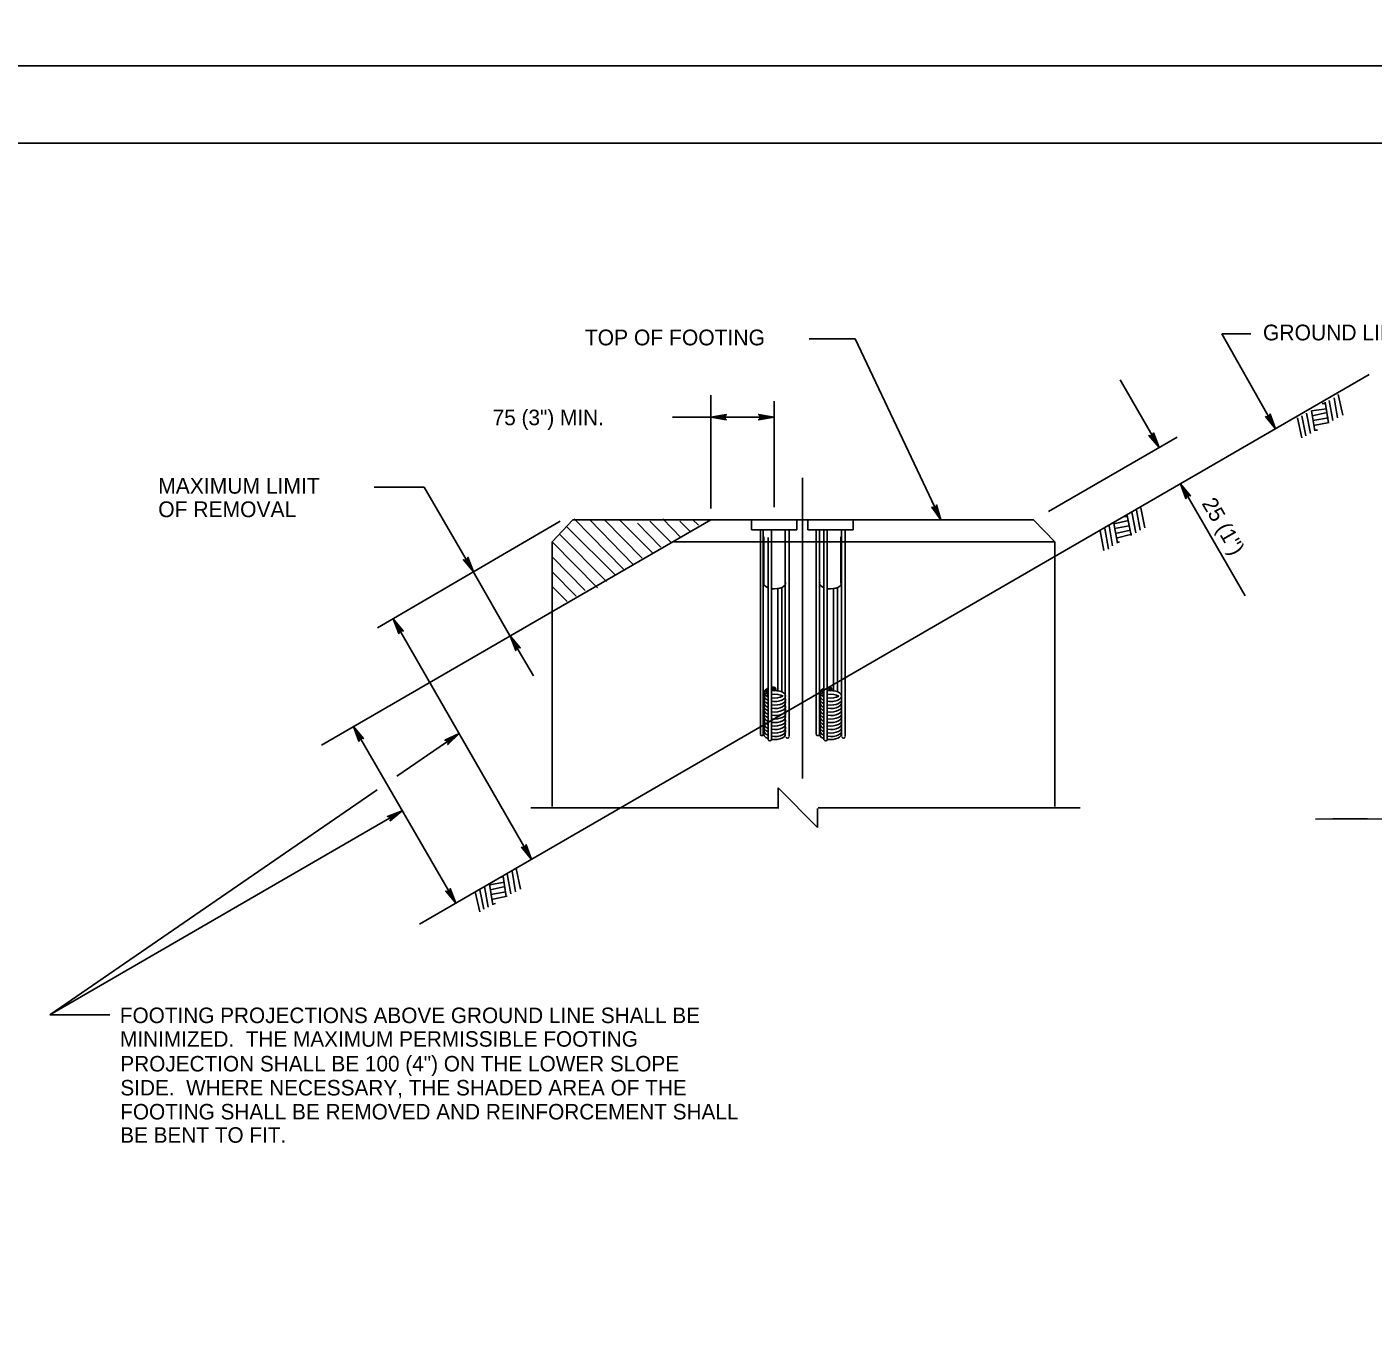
# Model space of a CAD drawing. Extents: x 637580 to 641008, y 294594 to 295782.
# Drawn here: x 640305.6 to 640565.8, y 294944.4 to 295195.1 of the extents above; entities that cross this region are included whole.
import ezdxf

# ---------------------------------------------------------------- set-up
doc = ezdxf.new("R2010")
doc.units = 0
for name, color, linetype in [('1', 7, 'Continuous'), ('2', 7, 'Continuous'), ('3', 7, 'Continuous'), ('PLT-BNDY', 7, 'Continuous')]:
    doc.layers.add(name, color=color, linetype=linetype)

# ---------------------------------------------------------------- blocks, each defined once
blk = doc.blocks.new('RARROW')
at = {"layer": '3'}
blk.add_lwpolyline([(-2.2695, 0.285), (-2.184875, 0.12075), (0, 0), (-2.2695, 0.285), (-2.38575, 0.384625), (0, 0), (-2.183125, -0.108), (-2.262875, -0.2705), (0, 0), (-2.38575, -0.379125), (-2.262875, -0.2705)], dxfattribs=at)

msp = doc.modelspace()

# ---------------------------------------------------------------- linework, layer by layer
at = {"layer": '1'}
for p, q in [((640143.31, 295172.63), (640929.31, 295172.63)), ((640559.02, 295124.06), (640559.9, 295120.06)), ((640556.52, 295122.31), (640555.9, 295122.31)), ((640556.52, 295122.56), (640557.15, 295118.56)), ((640557.27, 295122.93), (640558.02, 295119.06)), ((640558.27, 295123.43), (640558.9, 295119.56)), ((640551.15, 295119.56), (640552.02, 295115.68)), ((640552.02, 295119.93), (640552.77, 295116.06)), ((640552.9, 295120.43), (640553.65, 295116.56)), ((640556.77, 295121.31), (640553.9, 295120.93)), ((640553.9, 295120.93), (640554.52, 295117.06)), ((640556.9, 295120.56), (640554.02, 295119.93)), ((640557.15, 295119.56), (640554.15, 295119.06)), ((640557.27, 295118.68), (640554.27, 295118.06)), ((640555.02, 295117.18), (640554.52, 295117.18)), ((640518.4, 295100.56), (640517.77, 295100.43)), ((640518.27, 295100.68), (640519.02, 295096.81)), ((640519.15, 295101.31), (640519.9, 295097.31)), ((640520.02, 295101.68), (640520.77, 295097.81)), ((640520.9, 295102.18), (640521.65, 295098.31)), ((640513.9, 295098.18), (640514.65, 295094.18)), ((640514.77, 295098.68), (640515.4, 295094.81)), ((640518.52, 295099.68), (640515.65, 295099.06)), ((640515.65, 295099.18), (640516.4, 295095.31)), ((640518.65, 295098.68), (640515.77, 295098.18)), ((640513.02, 295097.68), (640513.77, 295093.93)), ((640518.9, 295097.81), (640516.02, 295097.18)), ((640519.15, 295097.06), (640516.15, 295096.31)), ((640516.77, 295095.56), (640516.4, 295095.43)), ((640397.65, 295030.81), (640397.02, 295030.68)), ((640397.65, 295030.93), (640398.27, 295026.93)), ((640398.4, 295031.43), (640399.15, 295027.56)), ((640399.4, 295031.93), (640400.02, 295027.93)), ((640400.15, 295032.43), (640401.02, 295028.43)), ((640392.27, 295027.93), (640393.15, 295024.06)), ((640393.15, 295028.31), (640393.9, 295024.56)), ((640394.02, 295028.93), (640394.77, 295024.93)), ((640397.9, 295029.81), (640395.02, 295029.31)), ((640395.02, 295029.43), (640395.65, 295025.43)), ((640398.02, 295028.93), (640395.15, 295028.31)), ((640398.15, 295027.93), (640395.27, 295027.43)), ((640398.4, 295027.06), (640395.4, 295026.43)), ((640396.15, 295025.68), (640395.65, 295025.56))]:
    msp.add_line(p, q, dxfattribs=at)
msp.add_ellipse((640561.36, 294260.59), major_axis=(0, 781.44), ratio=0.996388, start_param=6.016663, end_param=6.291815, dxfattribs=at)
at = {"layer": '2'}
for p, q in [((640456.8, 295134.86), (640465.69, 295134.86)), ((640465.69, 295134.86), (640482.26, 295099.81)), ((640536.54, 295135.81), (640546.9, 295117.43)), ((640536.54, 295135.81), (640542.15, 295135.81)), ((640381.52, 295021.68), (640565.02, 295127.93)), ((640516.9, 295126.93), (640524.4, 295113.81)), ((640437.77, 295102.06), (640437.77, 295123.93)), ((640450.02, 295102.31), (640450.02, 295122.81)), ((640430.37, 295119.68), (640450.02, 295119.68)), ((640503.02, 295101.43), (640527.9, 295115.81)), ((640372.75, 295106.18), (640382.4, 295106.18)), ((640382.4, 295106.18), (640392.15, 295089.43)), ((640455.52, 295107.93), (640455.52, 295049.81)), ((640528.54, 295106.81), (640541.02, 295085.14)), ((640362.52, 295056.31), (640437.77, 295099.81)), ((640373.4, 295078.93), (640408.65, 295099.56)), ((640407.15, 295095.56), (640411.15, 295099.81)), ((640409.9, 295098.56), (640419.4, 295089.06)), ((640500.15, 295099.81), (640411.15, 295099.81)), ((640411.4, 295100.06), (640420.9, 295090.31)), ((640414.4, 295099.81), (640422.77, 295091.18)), ((640417.27, 295099.81), (640424.52, 295092.43)), ((640420.27, 295099.68), (640426.65, 295093.31)), ((640423.65, 295099.18), (640428.15, 295094.56)), ((640426.02, 295099.56), (640430.15, 295095.43)), ((640428.52, 295100.06), (640432.02, 295096.43)), ((640431.77, 295099.56), (640433.9, 295097.43)), ((640434.27, 295099.93), (640435.4, 295098.81)), ((640454.4, 295099.81), (640445.65, 295099.81)), ((640445.65, 295099.81), (640445.65, 295097.93)), ((640454.4, 295097.93), (640445.65, 295097.93)), ((640447.4, 295097.93), (640447.4, 295058.31)), ((640447.9, 295058.31), (640447.9, 295097.93)), ((640452.9, 295057.93), (640452.9, 295097.93)), ((640454.4, 295099.81), (640454.4, 295097.93)), ((640465.27, 295099.81), (640456.52, 295099.81)), ((640456.52, 295099.81), (640456.52, 295097.93)), ((640465.27, 295097.93), (640456.52, 295097.93)), ((640458.15, 295097.93), (640458.15, 295058.31)), ((640458.77, 295058.31), (640458.77, 295097.93)), ((640459.65, 295097.93), (640459.65, 295057.31)), ((640460.27, 295057.18), (640460.27, 295097.93)), ((640463.02, 295097.93), (640463.02, 295057.93)), ((640463.77, 295057.93), (640463.77, 295097.93)), ((640465.27, 295099.81), (640465.27, 295097.93)), ((640500.15, 295099.81), (640504.27, 295095.56)), ((640407.15, 295095.56), (640407.15, 295044.43)), ((640407.15, 295095.56), (640415.9, 295086.68)), ((640408.52, 295097.06), (640417.65, 295087.93)), ((640504.27, 295095.56), (640430.65, 295095.56)), ((640448.02, 295087.56), (640448.02, 295096.56)), ((640448.9, 295096.43), (640448.9, 295057.31)), ((640449.52, 295057.18), (640449.52, 295097.81)), ((640452.15, 295097.68), (640452.15, 295057.93)), ((640452.15, 295087.56), (640452.15, 295096.56)), ((640458.77, 295087.56), (640458.77, 295096.56)), ((640462.9, 295087.56), (640462.9, 295096.56)), ((640504.27, 295095.56), (640504.27, 295044.43)), ((640407.15, 295092.68), (640413.52, 295086.18)), ((640392.15, 295089.43), (640398.9, 295077.56)), ((640407.15, 295089.81), (640411.77, 295085.06)), ((640407.15, 295086.93), (640410.02, 295084.06)), ((640450.77, 295086.56), (640450.77, 295066.68)), ((640451.52, 295066.56), (640451.52, 295086.56)), ((640461.52, 295086.56), (640461.52, 295066.68)), ((640462.27, 295066.56), (640462.27, 295086.56)), ((640376.4, 295080.68), (640403.15, 295034.18)), ((640398.9, 295077.56), (640403.52, 295069.68)), ((640368.72, 295059.89), (640388.5, 295025.72)), ((640377.08, 295050.26), (640389.13, 295058.54)), ((640448.9, 295057.56), (640448.9, 295057.31)), ((640449.52, 295057.31), (640449.52, 295057.56)), ((640450.15, 295057.43), (640450.15, 295057.43)), ((640450.15, 295057.43), (640450.15, 295057.43)), ((640459.65, 295057.56), (640459.65, 295057.31)), ((640460.27, 295057.31), (640460.27, 295057.56)), ((640460.9, 295057.43), (640460.9, 295057.43)), ((640460.9, 295057.43), (640460.9, 295057.43)), ((640310.02, 295004.18), (640373.3, 295047.67)), ((640450.78, 295044.01), (640450.78, 295048.01)), ((640450.78, 295048.01), (640458.41, 295040.38)), ((640310.02, 295004.18), (640378.14, 295043.61)), ((640450.9, 295044.18), (640403.02, 295044.18)), ((640458.41, 295040.38), (640458.41, 295044.01)), ((640509.15, 295044.18), (640458.52, 295044.18)), ((640310.02, 295004.18), (640321.65, 295004.18))]:
    msp.add_line(p, q, dxfattribs=at)
for centre, major_axis, ratio, start_param, end_param in [((640450.27, 295087.53), (2.27, 0), 0.460673, 2.912303, 4.028509), ((640449.97, 295087.54), (2.27, 0), 0.460673, 4.516666, 6.442696), ((640461.08, 295087.53), (2.27, 0), 0.460673, 2.912303, 4.028509), ((640460.78, 295087.54), (2.27, 0), 0.460673, 4.516666, 6.442696), ((640450.15, 295066.43), (-2.08, 0), 0.502134, 5.849045, 7.178118), ((640450.13, 295066.44), (-2.08, 0), 0.502134, 5.351446, 7.172319), ((640448.33, 295066.66), (0, 0.243), 0.996388, 3.791362, 5.77982), ((640448.53, 295066.83), (0, 0.243), 0.996388, 3.791362, 5.77982), ((640450.13, 295066.44), (-2.08, 0), 0.502134, 4.76759, 5.015799), ((640450.17, 295065.78), (-2.08, 0), 0.502134, 1.274353, 5.008427), ((640449.58, 295067.15), (0, 0.243), 0.996388, 3.791362, 5.77982), ((640449.87, 295067.15), (0, 0.243), 0.996388, 3.791362, 5.77982), ((640449.98, 295067.14), (0, 0.357), 0.996388, 3.239859, 6.022487), ((640460.96, 295066.43), (-2.08, 0), 0.502134, 5.849045, 7.178118), ((640460.94, 295066.44), (-2.08, 0), 0.502134, 5.351446, 7.172319), ((640459.14, 295066.66), (0, 0.243), 0.996388, 3.791362, 5.77982), ((640459.34, 295066.83), (0, 0.243), 0.996388, 3.791362, 5.77982), ((640460.94, 295066.44), (-2.08, 0), 0.502134, 4.76759, 5.015799), ((640460.98, 295065.78), (-2.08, 0), 0.502134, 1.274353, 5.008427), ((640460.39, 295067.15), (0, 0.243), 0.996388, 3.791362, 5.77982), ((640460.68, 295067.15), (0, 0.243), 0.996388, 3.791362, 5.77982), ((640460.79, 295067.14), (0, 0.357), 0.996388, 3.239859, 6.022487), ((640450.15, 295064.4), (-2.08, 0), 0.502134, 5.919723, 7.178118), ((640450.16, 295065.08), (-2.08, 0), 0.502134, 5.946798, 7.171813), ((640450.16, 295065.76), (-2.08, 0), 0.502134, 5.393334, 7.171813), ((640450.16, 295065.08), (-2.08, 0), 0.502134, 5.393334, 5.574261), ((640450.16, 295065.08), (-2.08, 0), 0.502134, 5.393334, 5.569266), ((640448.5, 295066.08), (0, 0.243), 0.996388, 3.791362, 5.77982), ((640450.16, 295065.08), (-2.08, 0), 0.502134, 3.844502, 5.011675), ((640450.15, 295066.43), (-2.08, 0), 0.502134, 1.274353, 2.407384), ((640450.15, 295064.4), (-2.08, 0), 0.502134, 1.274353, 3.486745), ((640450.16, 295063.73), (-2.08, 0), 0.502134, 1.27062, 3.503952), ((640450.17, 295065.07), (-2.08, 0), 0.502134, 1.274353, 3.473428), ((640450.13, 295066.44), (-2.08, 0), 0.502134, 1.299271, 2.390101), ((640460.96, 295064.4), (-2.08, 0), 0.502134, 5.919723, 7.178118), ((640460.97, 295065.08), (-2.08, 0), 0.502134, 5.946798, 7.171813), ((640460.97, 295065.76), (-2.08, 0), 0.502134, 5.393334, 7.171813), ((640460.97, 295065.08), (-2.08, 0), 0.502134, 5.393334, 5.574261), ((640460.97, 295065.08), (-2.08, 0), 0.502134, 5.393334, 5.569266), ((640459.31, 295066.08), (0, 0.243), 0.996388, 3.791362, 5.77982), ((640460.97, 295065.08), (-2.08, 0), 0.502134, 3.844502, 5.011675), ((640460.96, 295066.43), (-2.08, 0), 0.502134, 1.274353, 2.407384), ((640460.96, 295064.4), (-2.08, 0), 0.502134, 1.274353, 3.486745), ((640460.97, 295063.73), (-2.08, 0), 0.502134, 1.27062, 3.503952), ((640460.98, 295065.07), (-2.08, 0), 0.502134, 1.274353, 3.473428), ((640460.94, 295066.44), (-2.08, 0), 0.502134, 1.299271, 2.390101), ((640450.16, 295063.73), (-2.08, 0), 0.502134, 5.937119, 7.171813), ((640450.16, 295061.69), (-2.08, 0), 0.502134, 5.946798, 7.171813), ((640450.17, 295063.05), (-2.08, 0), 0.502134, 5.955741, 7.164478), ((640450.17, 295062.37), (-2.08, 0), 0.502134, 5.965552, 7.164478), ((640450.17, 295063.05), (-2.08, 0), 0.502134, 1.264877, 3.495986), ((640450.17, 295062.37), (-2.08, 0), 0.502134, 1.264877, 3.488314), ((640450.16, 295061.69), (-2.08, 0), 0.502134, 1.27062, 3.451822), ((640460.97, 295063.73), (-2.08, 0), 0.502134, 5.937119, 7.171813), ((640460.97, 295061.69), (-2.08, 0), 0.502134, 5.946798, 7.171813), ((640460.98, 295063.05), (-2.08, 0), 0.502134, 5.955741, 7.164478), ((640460.98, 295062.37), (-2.08, 0), 0.502134, 5.965552, 7.164478), ((640460.98, 295063.05), (-2.08, 0), 0.502134, 1.264877, 3.495986), ((640460.98, 295062.37), (-2.08, 0), 0.502134, 1.264877, 3.488314), ((640460.97, 295061.69), (-2.08, 0), 0.502134, 1.27062, 3.451822), ((640450.15, 295060.34), (-2.08, 0), 0.502134, 5.938832, 7.178118), ((640450.17, 295061.02), (-2.08, 0), 0.502134, 5.963088, 7.164478), ((640450.17, 295059.66), (-2.08, 0), 0.502134, 5.96802, 7.164478), ((640450.17, 295058.99), (-2.08, 0), 0.502134, 5.972967, 7.164478), ((640450.17, 295061.02), (-2.08, 0), 0.502134, 1.264877, 3.483183), ((640450.15, 295060.34), (-2.08, 0), 0.502134, 1.274353, 3.465537), ((640450.17, 295059.66), (-2.08, 0), 0.502134, 1.264877, 3.503379), ((640450.17, 295058.99), (-2.08, 0), 0.502134, 1.264877, 3.485633), ((640460.96, 295060.34), (-2.08, 0), 0.502134, 5.938832, 7.178118), ((640460.98, 295061.02), (-2.08, 0), 0.502134, 5.963088, 7.164478), ((640460.98, 295059.66), (-2.08, 0), 0.502134, 5.96802, 7.164478), ((640460.98, 295058.99), (-2.08, 0), 0.502134, 5.972967, 7.164478), ((640460.98, 295061.02), (-2.08, 0), 0.502134, 1.264877, 3.483183), ((640460.96, 295060.34), (-2.08, 0), 0.502134, 1.274353, 3.465537), ((640460.98, 295059.66), (-2.08, 0), 0.502134, 1.264877, 3.503379), ((640460.98, 295058.99), (-2.08, 0), 0.502134, 1.264877, 3.485633), ((640447.68, 295058.55), (0, -0.425), 0.996388, 5.360294, 7.206077), ((640450.1, 295058.39), (-2.08, 0), 0.502134, 5.966419, 7.210371), ((640449.2, 295057.56), (0, -0.425), 0.996388, 5.360294, 7.206077), ((640450.1, 295058.39), (-2.08, 0), 0.502134, 1.288679, 3.37371), ((640452.61, 295058.05), (0, -0.425), 0.996388, 5.360294, 7.206077), ((640458.49, 295058.55), (0, -0.425), 0.996388, 5.360294, 7.206077), ((640460.91, 295058.39), (-2.08, 0), 0.502134, 5.966419, 7.210371), ((640460.01, 295057.56), (0, -0.425), 0.996388, 5.360294, 7.206077), ((640460.91, 295058.39), (-2.08, 0), 0.502134, 1.288679, 3.37371), ((640463.42, 295058.05), (0, -0.425), 0.996388, 5.360294, 7.206077)]:
    msp.add_ellipse(centre, major_axis=major_axis, ratio=ratio, start_param=start_param, end_param=end_param, dxfattribs=at)
at = {"layer": 'PLT-BNDY'}
for points in [[(640103.31, 295781.63), (640944.31, 295781.63), (640944.31, 295187.63), (640103.31, 295187.63)], [(640103.31, 295187.63), (640944.31, 295187.63), (640944.31, 294593.63), (640103.31, 294593.63)]]:
    msp.add_lwpolyline(points, close=True, dxfattribs=at)

# ---------------------------------------------------------------- block references
at = {"layer": '2'}
for p, xscale, yscale, rotation in [((640437.77, 295119.68), 1.2574347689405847, 1.3092961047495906, 180), ((640546.9, 295117.43), 1.257434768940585, 1.3092961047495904, -60.41609152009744), ((640524.4, 295113.81), 1.2574347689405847, 1.3092961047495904, -59.68635191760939), ((640528.54, 295106.81), 1.257434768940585, 1.3092961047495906, 120.03222654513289), ((640482.26, 295099.81), 1.2574347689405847, 1.3092961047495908, -64.63743865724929), ((640391.94, 295089.78), 1.2574347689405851, 1.3092961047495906, -59.52957855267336), ((640376.4, 295080.68), 1.2574347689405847, 1.3092961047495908, 120.6554124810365), ((640398.99, 295077.39), 1.2574347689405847, 1.3092961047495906, 120.8985177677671), ((640368.72, 295059.89), 1.2574347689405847, 1.3092961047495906, 120.1970552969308), ((640389.13, 295058.54), 1.2574347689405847, 1.3092961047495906, 35.18341363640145), ((640378.14, 295043.61), 1.257434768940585, 1.3092961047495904, 30.52246453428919), ((640403.15, 295034.18), 1.257434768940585, 1.3092961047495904, -60.00424236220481), ((640388.5, 295025.72), 1.2574347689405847, 1.3092961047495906, -59.79079898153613)]:
    msp.add_blockref('RARROW', p, dxfattribs=dict(at, xscale=xscale, yscale=yscale, rotation=rotation))
at = {"layer": '2', "xscale": 1.2574347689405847, "yscale": 1.3092961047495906}
msp.add_blockref('RARROW', (640450.02, 295119.68), dxfattribs=at)

# ---------------------------------------------------------------- texts
at = {"layer": '3'}
for s, height, p in [('GROUND LINE', 3.0442, (640544.49, 295134.53)), ('TOP OF FOOTING', 3.0427, (640413.44, 295133.57)), ('75 (3") MIN.', 3, (640395.63, 295118.13)), ('MAXIMUM LIMIT', 3.0427, (640331, 295104.9)), ('OF REMOVAL', 3.043, (640331, 295100.36)), ('FOOTING PROJECTIONS ABOVE GROUND LINE SHALL BE', 3, (640323.58, 295002.55)), ('MINIMIZED.  THE MAXIMUM PERMISSIBLE FOOTING', 3, (640323.62, 294997.99)), ('PROJECTION SHALL BE 100 (4") ON THE LOWER SLOPE', 3, (640323.68, 294993.2)), ('SIDE.  WHERE NECESSARY, THE SHADED AREA OF THE', 3, (640323.68, 294988.56)), ('FOOTING SHALL BE REMOVED AND REINFORCEMENT SHALL', 3, (640323.65, 294983.92)), ('BE BENT TO FIT.', 3, (640323.65, 294979.42))]:
    msp.add_text(s, height=height, dxfattribs=at).set_placement(p)
msp.add_text('25 (1")', height=3, rotation=299.9419, dxfattribs=at).set_placement((640532.58, 295103.03))

doc.saveas('drawing.dxf')
